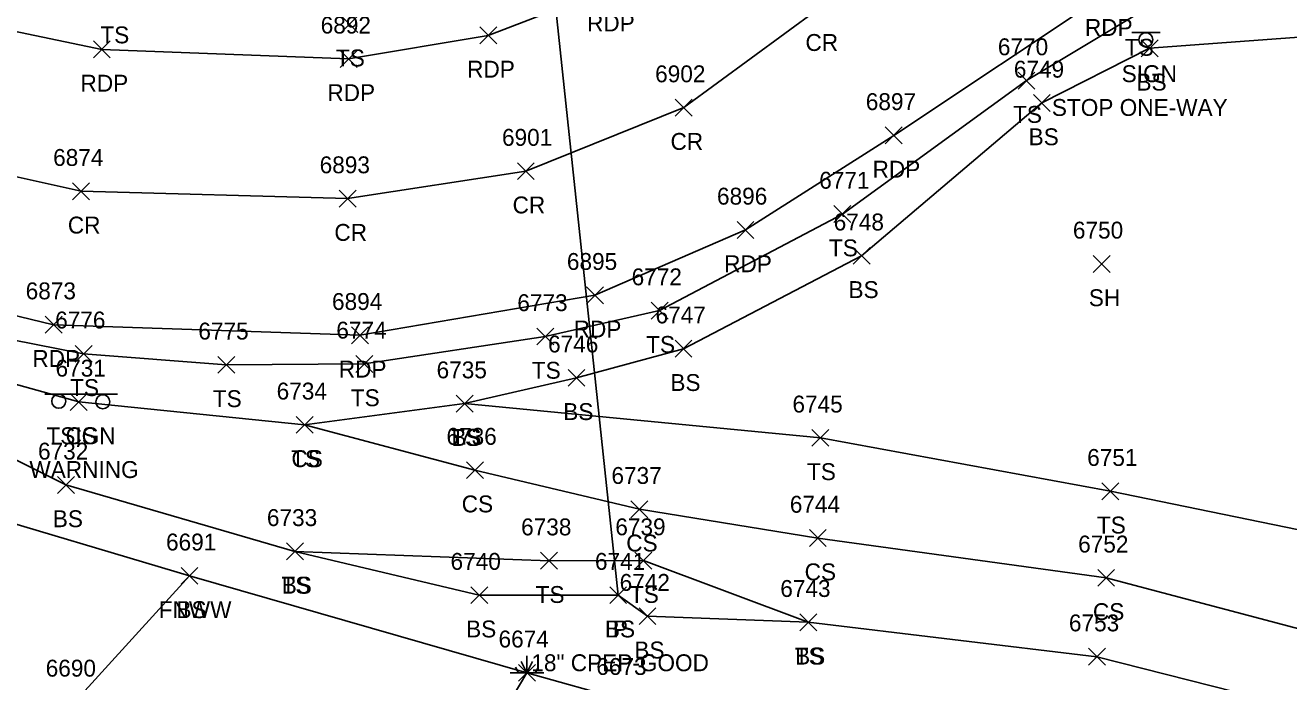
# Model space of a CAD drawing. Extents: x 1505656 to 1508446, y 700805 to 703031.
# Drawn here: x 1507471 to 1507620.5, y 701219.6 to 701297.3 of the extents above; entities that cross this region are included whole.
import ezdxf

# ---------------------------------------------------------------- set-up
doc = ezdxf.new("R2010")
doc.units = 0
for name, color, linetype in [('D_A', 7, 'Continuous'), ('D_C', 7, 'Continuous'), ('D_I', 7, 'Continuous'), ('D_TIC', 7, 'Continuous'), ('DCP', 7, 'Continuous'), ('L_A', 7, 'Continuous'), ('L_I', 7, 'Continuous'), ('L_TIC', 7, 'Continuous'), ('LELB', 7, 'Continuous'), ('LFNC', 7, 'Continuous'), ('LWET', 7, 'Continuous'), ('P_A', 7, 'Continuous'), ('P_I', 7, 'Continuous'), ('P_TIC', 7, 'Continuous'), ('PET', 7, 'Continuous'), ('PRC', 7, 'Continuous'), ('S_A', 7, 'Continuous'), ('S_C', 7, 'Continuous'), ('S_I', 7, 'Continuous'), ('SSGN', 7, 'Continuous')]:
    doc.layers.add(name, color=color, linetype=linetype)

msp = doc.modelspace()

# ---------------------------------------------------------------- linework, layer by layer
at = {"layer": 'D_TIC'}
for points in [[(1507540.19, 701228.88), (1507542.19, 701230.88)], [(1507542.19, 701228.88), (1507540.19, 701230.88)]]:
    msp.add_lwpolyline(points, dxfattribs=at)
at = {"layer": 'DCP'}
msp.add_lwpolyline([(1507541.19, 701229.88), (1507532.37, 701313)], dxfattribs=at)
at = {"layer": 'L_TIC'}
for points in [[(1507508.4, 701296.47), (1507510.4, 701298.47)], [(1507510.4, 701296.47), (1507508.4, 701298.47)], [(1507603.09, 701293.61), (1507605.09, 701295.61)], [(1507605.09, 701293.61), (1507603.09, 701295.61)], [(1507588.52, 701289.79), (1507590.52, 701291.79)], [(1507590.52, 701289.79), (1507588.52, 701291.79)], [(1507590.33, 701287.14), (1507592.33, 701289.14)], [(1507592.33, 701287.14), (1507590.33, 701289.14)], [(1507566.73, 701273.99), (1507568.73, 701275.99)], [(1507568.73, 701273.99), (1507566.73, 701275.99)], [(1507569.01, 701269.05), (1507571.01, 701271.05)], [(1507571.01, 701269.05), (1507569.01, 701271.05)], [(1507597.4, 701268.09), (1507599.4, 701270.09)], [(1507599.4, 701268.09), (1507597.4, 701270.09)], [(1507545.1, 701262.56), (1507547.1, 701264.56)], [(1507547.1, 701262.56), (1507545.1, 701264.56)], [(1507531.57, 701259.5), (1507533.57, 701261.5)], [(1507533.57, 701259.5), (1507531.57, 701261.5)], [(1507476.93, 701257.45), (1507478.93, 701259.45)], [(1507478.93, 701257.45), (1507476.93, 701259.45)], [(1507547.93, 701258.05), (1507549.93, 701260.05)], [(1507549.93, 701258.05), (1507547.93, 701260.05)], [(1507493.82, 701256.14), (1507495.82, 701258.14)], [(1507495.82, 701256.14), (1507493.82, 701258.14)], [(1507510.15, 701256.25), (1507512.15, 701258.25)], [(1507512.15, 701256.25), (1507510.15, 701258.25)], [(1507535.26, 701254.61), (1507537.26, 701256.61)], [(1507537.26, 701254.61), (1507535.26, 701256.61)], [(1507476.36, 701251.75), (1507478.36, 701253.75)], [(1507478.36, 701251.75), (1507476.36, 701253.75)], [(1507522.02, 701251.55), (1507524.02, 701253.55)], [(1507524.02, 701251.55), (1507522.02, 701253.55)], [(1507522.02, 701251.55), (1507524.02, 701253.55)], [(1507524.02, 701251.55), (1507522.02, 701253.55)], [(1507503.09, 701249.04), (1507505.09, 701251.04)], [(1507505.09, 701249.04), (1507503.09, 701251.04)], [(1507503.09, 701249.04), (1507505.09, 701251.04)], [(1507505.09, 701249.04), (1507503.09, 701251.04)], [(1507564.13, 701247.5), (1507566.13, 701249.5)], [(1507566.13, 701247.5), (1507564.13, 701249.5)], [(1507523.24, 701243.68), (1507525.24, 701245.68)], [(1507525.24, 701243.68), (1507523.24, 701245.68)], [(1507474.85, 701241.93), (1507476.85, 701243.93)], [(1507476.85, 701241.93), (1507474.85, 701243.93)], [(1507598.44, 701241.18), (1507600.44, 701243.18)], [(1507600.44, 701241.18), (1507598.44, 701243.18)], [(1507542.71, 701239.05), (1507544.71, 701241.05)], [(1507544.71, 701239.05), (1507542.71, 701241.05)], [(1507563.82, 701235.64), (1507565.82, 701237.64)], [(1507565.82, 701235.64), (1507563.82, 701237.64)], [(1507501.94, 701234.06), (1507503.94, 701236.06)], [(1507503.94, 701234.06), (1507501.94, 701236.06)], [(1507501.94, 701234.06), (1507503.94, 701236.06)], [(1507503.94, 701234.06), (1507501.94, 701236.06)], [(1507532.02, 701232.96), (1507534.02, 701234.96)], [(1507534.02, 701232.96), (1507532.02, 701234.96)], [(1507543.18, 701232.97), (1507545.18, 701234.97)], [(1507545.18, 701232.97), (1507543.18, 701234.97)], [(1507489.47, 701231.17), (1507491.47, 701233.17)], [(1507491.47, 701231.17), (1507489.47, 701233.17)], [(1507489.47, 701231.17), (1507491.47, 701233.17)], [(1507491.47, 701231.17), (1507489.47, 701233.17)], [(1507597.94, 701230.93), (1507599.94, 701232.93)], [(1507599.94, 701230.93), (1507597.94, 701232.93)], [(1507523.76, 701228.88), (1507525.76, 701230.88)], [(1507525.76, 701228.88), (1507523.76, 701230.88)], [(1507540.19, 701228.88), (1507542.19, 701230.88)], [(1507542.19, 701228.88), (1507540.19, 701230.88)], [(1507543.67, 701226.39), (1507545.67, 701228.39)], [(1507545.67, 701226.39), (1507543.67, 701228.39)], [(1507562.69, 701225.67), (1507564.69, 701227.67)], [(1507564.69, 701225.67), (1507562.69, 701227.67)], [(1507562.69, 701225.67), (1507564.69, 701227.67)], [(1507564.69, 701225.67), (1507562.69, 701227.67)], [(1507596.85, 701221.6), (1507598.85, 701223.6)], [(1507598.85, 701221.6), (1507596.85, 701223.6)], [(1507529.4, 701219.69), (1507531.4, 701221.69)], [(1507531.4, 701219.69), (1507529.4, 701221.69)]]:
    msp.add_lwpolyline(points, dxfattribs=at)
at = {"layer": 'LELB'}
for points in [[(1507664.64, 701288.76), (1507647.23, 701299.02), (1507624.46, 701303.4), (1507602.75, 701298.73), (1507589.52, 701290.79), (1507567.73, 701274.99), (1507546.1, 701263.56), (1507532.57, 701260.5), (1507511.15, 701257.25), (1507494.82, 701257.14), (1507477.93, 701258.45), (1507454.88, 701263), (1507442.63, 701266.73), (1507416.76, 701276.5), (1507380.5, 701295.43), (1507349.66, 701313.74), (1507307.1, 701338.01), (1507263.23, 701366.42), (1507214.44, 701398.2)], [(1507206.22, 701385.53), (1507252.86, 701358.93), (1507301.28, 701331.26), (1507345.08, 701308.55), (1507379.28, 701292.34), (1507415.34, 701274.6), (1507442.69, 701262.41), (1507477.36, 701252.75), (1507504.09, 701250.04), (1507524.24, 701244.68), (1507543.71, 701240.05), (1507564.82, 701236.64), (1507598.94, 701231.93), (1507652.74, 701217.67)], [(1507196.76, 701372), (1507244.87, 701347.76), (1507297.87, 701319.93), (1507344.77, 701301.89), (1507376.8, 701287.99), (1507414.57, 701272.26), (1507441.62, 701260.06), (1507475.85, 701242.93), (1507502.94, 701235.06), (1507524.76, 701229.88), (1507541.19, 701229.88), (1507544.67, 701227.39), (1507563.69, 701226.67), (1507597.85, 701222.6), (1507649.46, 701209.48)], [(1507523.02, 701252.55), (1507536.26, 701255.61), (1507548.93, 701259.05), (1507570.01, 701270.05), (1507591.33, 701288.14), (1507604.09, 701294.61), (1507622.28, 701295.96), (1507643.83, 701292.94), (1507664.64, 701288.76)], [(1507504.09, 701250.04), (1507523.02, 701252.55), (1507565.13, 701248.5), (1507599.44, 701242.18), (1507657.3, 701230.32)], [(1507502.94, 701235.06), (1507533.02, 701233.96), (1507544.18, 701233.97), (1507563.69, 701226.67)], [(1507420.38, 701169.64), (1507443.62, 701199.85), (1507476.89, 701217.24), (1507490.47, 701232.17)]]:
    msp.add_lwpolyline(points, dxfattribs=at)
at = {"layer": 'LFNC'}
msp.add_lwpolyline([(1507721.58, 701162.07), (1507708.46, 701169.26), (1507682.76, 701176.46), (1507629.63, 701192.11), (1507592.19, 701203.04), (1507562.07, 701211.89), (1507541.96, 701217.44), (1507530.4, 701220.69), (1507490.47, 701232.17), (1507463.39, 701240.21), (1507439.34, 701246.9), (1507401.64, 701257.79), (1507360.86, 701269.69), (1507318.6, 701282.5), (1507279.07, 701293.63), (1507239.17, 701305.1), (1507200.8, 701316.65)], dxfattribs=at)
at = {"layer": 'LWET'}
for p, q in [((1507530.4, 701220.69), (1507529.73, 701222.02)), ((1507530.4, 701220.69), (1507530.4, 701222.69)), ((1507530.4, 701220.69), (1507531.06, 701222.02)), ((1507532.4, 701220.69), (1507528.4, 701220.69)), ((1507529.4, 701220.69), (1507529.06, 701221.35)), ((1507531.4, 701220.69), (1507531.73, 701221.35))]:
    msp.add_line(p, q, dxfattribs=at)
msp.add_lwpolyline([(1507530.4, 701220.69), (1507517.19, 701198.48), (1507502.96, 701183.94), (1507479.97, 701162.91), (1507459.81, 701143.66)], dxfattribs=at)
at = {"layer": 'P_TIC'}
for points in [[(1507524.83, 701295.14), (1507526.83, 701297.14)], [(1507526.83, 701295.14), (1507524.83, 701297.14)], [(1507479.09, 701293.48), (1507481.09, 701295.48)], [(1507481.09, 701293.48), (1507479.09, 701295.48)], [(1507508.29, 701292.36), (1507510.29, 701294.36)], [(1507510.29, 701292.36), (1507508.29, 701294.36)], [(1507547.96, 701286.59), (1507549.96, 701288.59)], [(1507549.96, 701286.59), (1507547.96, 701288.59)], [(1507572.81, 701283.3), (1507574.81, 701285.3)], [(1507574.81, 701283.3), (1507572.81, 701285.3)], [(1507529.27, 701279.07), (1507531.27, 701281.07)], [(1507531.27, 701279.07), (1507529.27, 701281.07)], [(1507476.64, 701276.69), (1507478.64, 701278.69)], [(1507478.64, 701276.69), (1507476.64, 701278.69)], [(1507508.18, 701275.82), (1507510.18, 701277.82)], [(1507510.18, 701275.82), (1507508.18, 701277.82)], [(1507555.26, 701272.11), (1507557.26, 701274.11)], [(1507557.26, 701272.11), (1507555.26, 701274.11)], [(1507537.44, 701264.38), (1507539.44, 701266.38)], [(1507539.44, 701264.38), (1507537.44, 701266.38)], [(1507473.38, 701260.9), (1507475.38, 701262.9)], [(1507475.38, 701260.9), (1507473.38, 701262.9)], [(1507509.64, 701259.64), (1507511.64, 701261.64)], [(1507511.64, 701259.64), (1507509.64, 701261.64)]]:
    msp.add_lwpolyline(points, dxfattribs=at)
at = {"layer": 'PET'}
for points in [[(1507231.61, 701427.39), (1507272.91, 701402.71), (1507311.8, 701378.29), (1507343.21, 701359.04), (1507374.88, 701340.26), (1507401.32, 701325.13), (1507427.17, 701310.75), (1507459.87, 701298.7), (1507480.09, 701294.48), (1507509.29, 701293.36), (1507525.83, 701296.14), (1507540.02, 701301.61), (1507551.73, 701310.36)], [(1507215.48, 701400.74), (1507258.54, 701373.9), (1507294.19, 701351.56), (1507327.49, 701331.46), (1507359.99, 701311.61), (1507385.1, 701296.57), (1507413.33, 701281.68), (1507446.05, 701268.76), (1507474.38, 701261.9), (1507510.64, 701260.64), (1507538.44, 701265.38), (1507556.26, 701273.11), (1507573.81, 701284.3)], [(1507573.81, 701284.3), (1507598.94, 701301.08)]]:
    msp.add_lwpolyline(points, dxfattribs=at)
at = {"layer": 'PRC'}
msp.add_lwpolyline([(1507224.48, 701413.97), (1507267.93, 701386.51), (1507302.71, 701364.98), (1507334.78, 701345.63), (1507366.2, 701326.16), (1507393.17, 701310.52), (1507419.83, 701295.27), (1507450.97, 701283.62), (1507477.64, 701277.69), (1507509.18, 701276.82), (1507530.27, 701280.07), (1507548.96, 701287.59), (1507564.92, 701299.3)], dxfattribs=at)
at = {"layer": 'SSGN'}
for p, q in [((1507602, 701296.47), (1507605.33, 701296.47)), ((1507603.64, 701295.63), (1507603.64, 701295.63)), ((1507473.34, 701253.67), (1507481.94, 701253.67)), ((1507477.36, 701252.77), (1507477.36, 701252.77))]:
    msp.add_line(p, q, dxfattribs=at)
for centre in [(1507603.64, 701295.63), (1507475, 701252.84), (1507480.21, 701252.77)]:
    msp.add_circle(centre, 0.833, dxfattribs=at)

# ---------------------------------------------------------------- texts
at = {"layer": 'D_A'}
msp.add_text('P', height=2, dxfattribs=at).set_placement((1507540.57, 701224.88))
at = {"layer": 'D_C'}
msp.add_text('18" CPEP-GOOD', height=2, dxfattribs=at).set_placement((1507530.92, 701220.88))
at = {"layer": 'D_I'}
msp.add_text('6741', height=2, dxfattribs=at).set_placement((1507538.45, 701232.88))
at = {"layer": 'L_A'}
for s, p in [('TS', (1507479.92, 701295.2)), ('TS', (1507601.16, 701293.73)), ('TS', (1507507.8, 701292.47)), ('BS', (1507602.53, 701289.61)), ('TS', (1507587.93, 701285.79)), ('BS', (1507589.77, 701283.14)), ('TS', (1507566.14, 701269.99)), ('BS', (1507568.45, 701265.05)), ('SH', (1507596.89, 701264.09)), ('TS', (1507544.51, 701258.56)), ('TS', (1507530.98, 701255.5)), ('TS', (1507476.34, 701253.45)), ('BS', (1507547.37, 701254.05)), ('TS', (1507493.23, 701252.14)), ('TS', (1507509.56, 701252.25)), ('BS', (1507534.7, 701250.61)), ('CS', (1507475.8, 701247.75)), ('TS', (1507521.43, 701247.55)), ('BS', (1507521.46, 701247.55)), ('TS', (1507502.5, 701245.04)), ('CS', (1507502.53, 701245.04)), ('TS', (1507563.54, 701243.5)), ('CS', (1507522.68, 701239.68)), ('BS', (1507474.29, 701237.93)), ('TS', (1507597.85, 701237.18)), ('CS', (1507542.15, 701235.05)), ('CS', (1507563.26, 701231.64)), ('TS', (1507501.35, 701230.06)), ('BS', (1507501.38, 701230.06)), ('TS', (1507531.43, 701228.96)), ('TS', (1507542.59, 701228.97)), ('FNWW', (1507486.82, 701227.17)), ('BS', (1507488.92, 701227.17)), ('CS', (1507597.38, 701226.93)), ('BS', (1507523.2, 701224.88)), ('BS', (1507539.63, 701224.88)), ('BS', (1507543.11, 701222.39)), ('TS', (1507562.1, 701221.67)), ('BS', (1507562.13, 701221.67))]:
    msp.add_text(s, height=2, dxfattribs=at).set_placement(p)
at = {"layer": 'L_I'}
for s, p in [('6770', (1507586.13, 701293.79)), ('6749', (1507588.02, 701291.14)), ('6771', (1507564.99, 701277.99)), ('6748', (1507566.7, 701273.05)), ('6750', (1507595.01, 701272.09)), ('6772', (1507542.79, 701266.56)), ('6773', (1507529.26, 701263.5)), ('6747', (1507545.62, 701262.05)), ('6776', (1507474.57, 701261.45)), ('6775', (1507491.51, 701260.14)), ('6774', (1507507.84, 701260.25)), ('6746', (1507532.9, 701258.61)), ('6731', (1507474.62, 701255.75)), ('6735', (1507519.71, 701255.55)), ('6735', (1507519.71, 701255.55)), ('6734', (1507500.78, 701253.04)), ('6734', (1507500.78, 701253.04)), ('6745', (1507561.82, 701251.5)), ('6736', (1507520.88, 701247.68)), ('6732', (1507472.54, 701245.93)), ('6751', (1507596.7, 701245.18)), ('6737', (1507540.4, 701243.05)), ('6744', (1507561.51, 701239.64)), ('6733', (1507499.63, 701238.06)), ('6733', (1507499.63, 701238.06)), ('6738', (1507529.71, 701236.96)), ('6739', (1507540.86, 701236.97)), ('6691', (1507487.69, 701235.17)), ('6691', (1507487.69, 701235.17)), ('6752', (1507595.63, 701234.93)), ('6740', (1507521.36, 701232.88)), ('6741', (1507538.45, 701232.88)), ('6742', (1507541.37, 701230.39)), ('6743', (1507560.38, 701229.67)), ('6743', (1507560.38, 701229.67)), ('6753', (1507594.54, 701225.6)), ('6674', (1507527.04, 701223.69)), ('6674', (1507527.04, 701223.69)), ('6690', (1507473.45, 701220.24)), ('6673', (1507538.61, 701220.44))]:
    msp.add_text(s, height=2, dxfattribs=at).set_placement(p)
at = {"layer": 'P_A'}
for s, p in [('RDP', (1507537.51, 701296.61)), ('RDP', (1507596.43, 701296.08)), ('CR', (1507563.36, 701294.3)), ('RDP', (1507523.32, 701291.14)), ('RDP', (1507477.57, 701289.48)), ('RDP', (1507506.78, 701288.36)), ('CR', (1507547.39, 701282.59)), ('RDP', (1507571.3, 701279.3)), ('CR', (1507528.7, 701275.07)), ('CR', (1507476.07, 701272.69)), ('CR', (1507507.61, 701271.82)), ('RDP', (1507553.74, 701268.11)), ('RDP', (1507535.93, 701260.38)), ('RDP', (1507471.87, 701256.9)), ('RDP', (1507508.13, 701255.64))]:
    msp.add_text(s, height=2, dxfattribs=at).set_placement(p)
at = {"layer": 'P_I'}
for s, p in [('6892', (1507505.99, 701296.36)), ('6902', (1507545.57, 701290.59)), ('6897', (1507570.5, 701287.3)), ('6901', (1507527.45, 701283.07)), ('6874', (1507474.33, 701280.69)), ('6893', (1507505.87, 701279.82)), ('6896', (1507552.89, 701276.11)), ('6895', (1507535.13, 701268.38)), ('6873', (1507471.08, 701264.9)), ('6894', (1507507.33, 701263.64))]:
    msp.add_text(s, height=2, dxfattribs=at).set_placement(p)
at = {"layer": 'S_A'}
for s, p in [('SIGN', (1507600.78, 701290.61)), ('TSIGN', (1507473.54, 701247.75))]:
    msp.add_text(s, height=2, dxfattribs=at).set_placement(p)
at = {"layer": 'S_C'}
for s, p in [('STOP ONE-WAY', (1507592.52, 701286.61)), ('WARNING', (1507471.52, 701243.75))]:
    msp.add_text(s, height=2, dxfattribs=at).set_placement(p)
at = {"layer": 'S_I'}
msp.add_text('6731', height=2, dxfattribs=at).set_placement((1507474.62, 701255.75))

doc.saveas('drawing.dxf')
